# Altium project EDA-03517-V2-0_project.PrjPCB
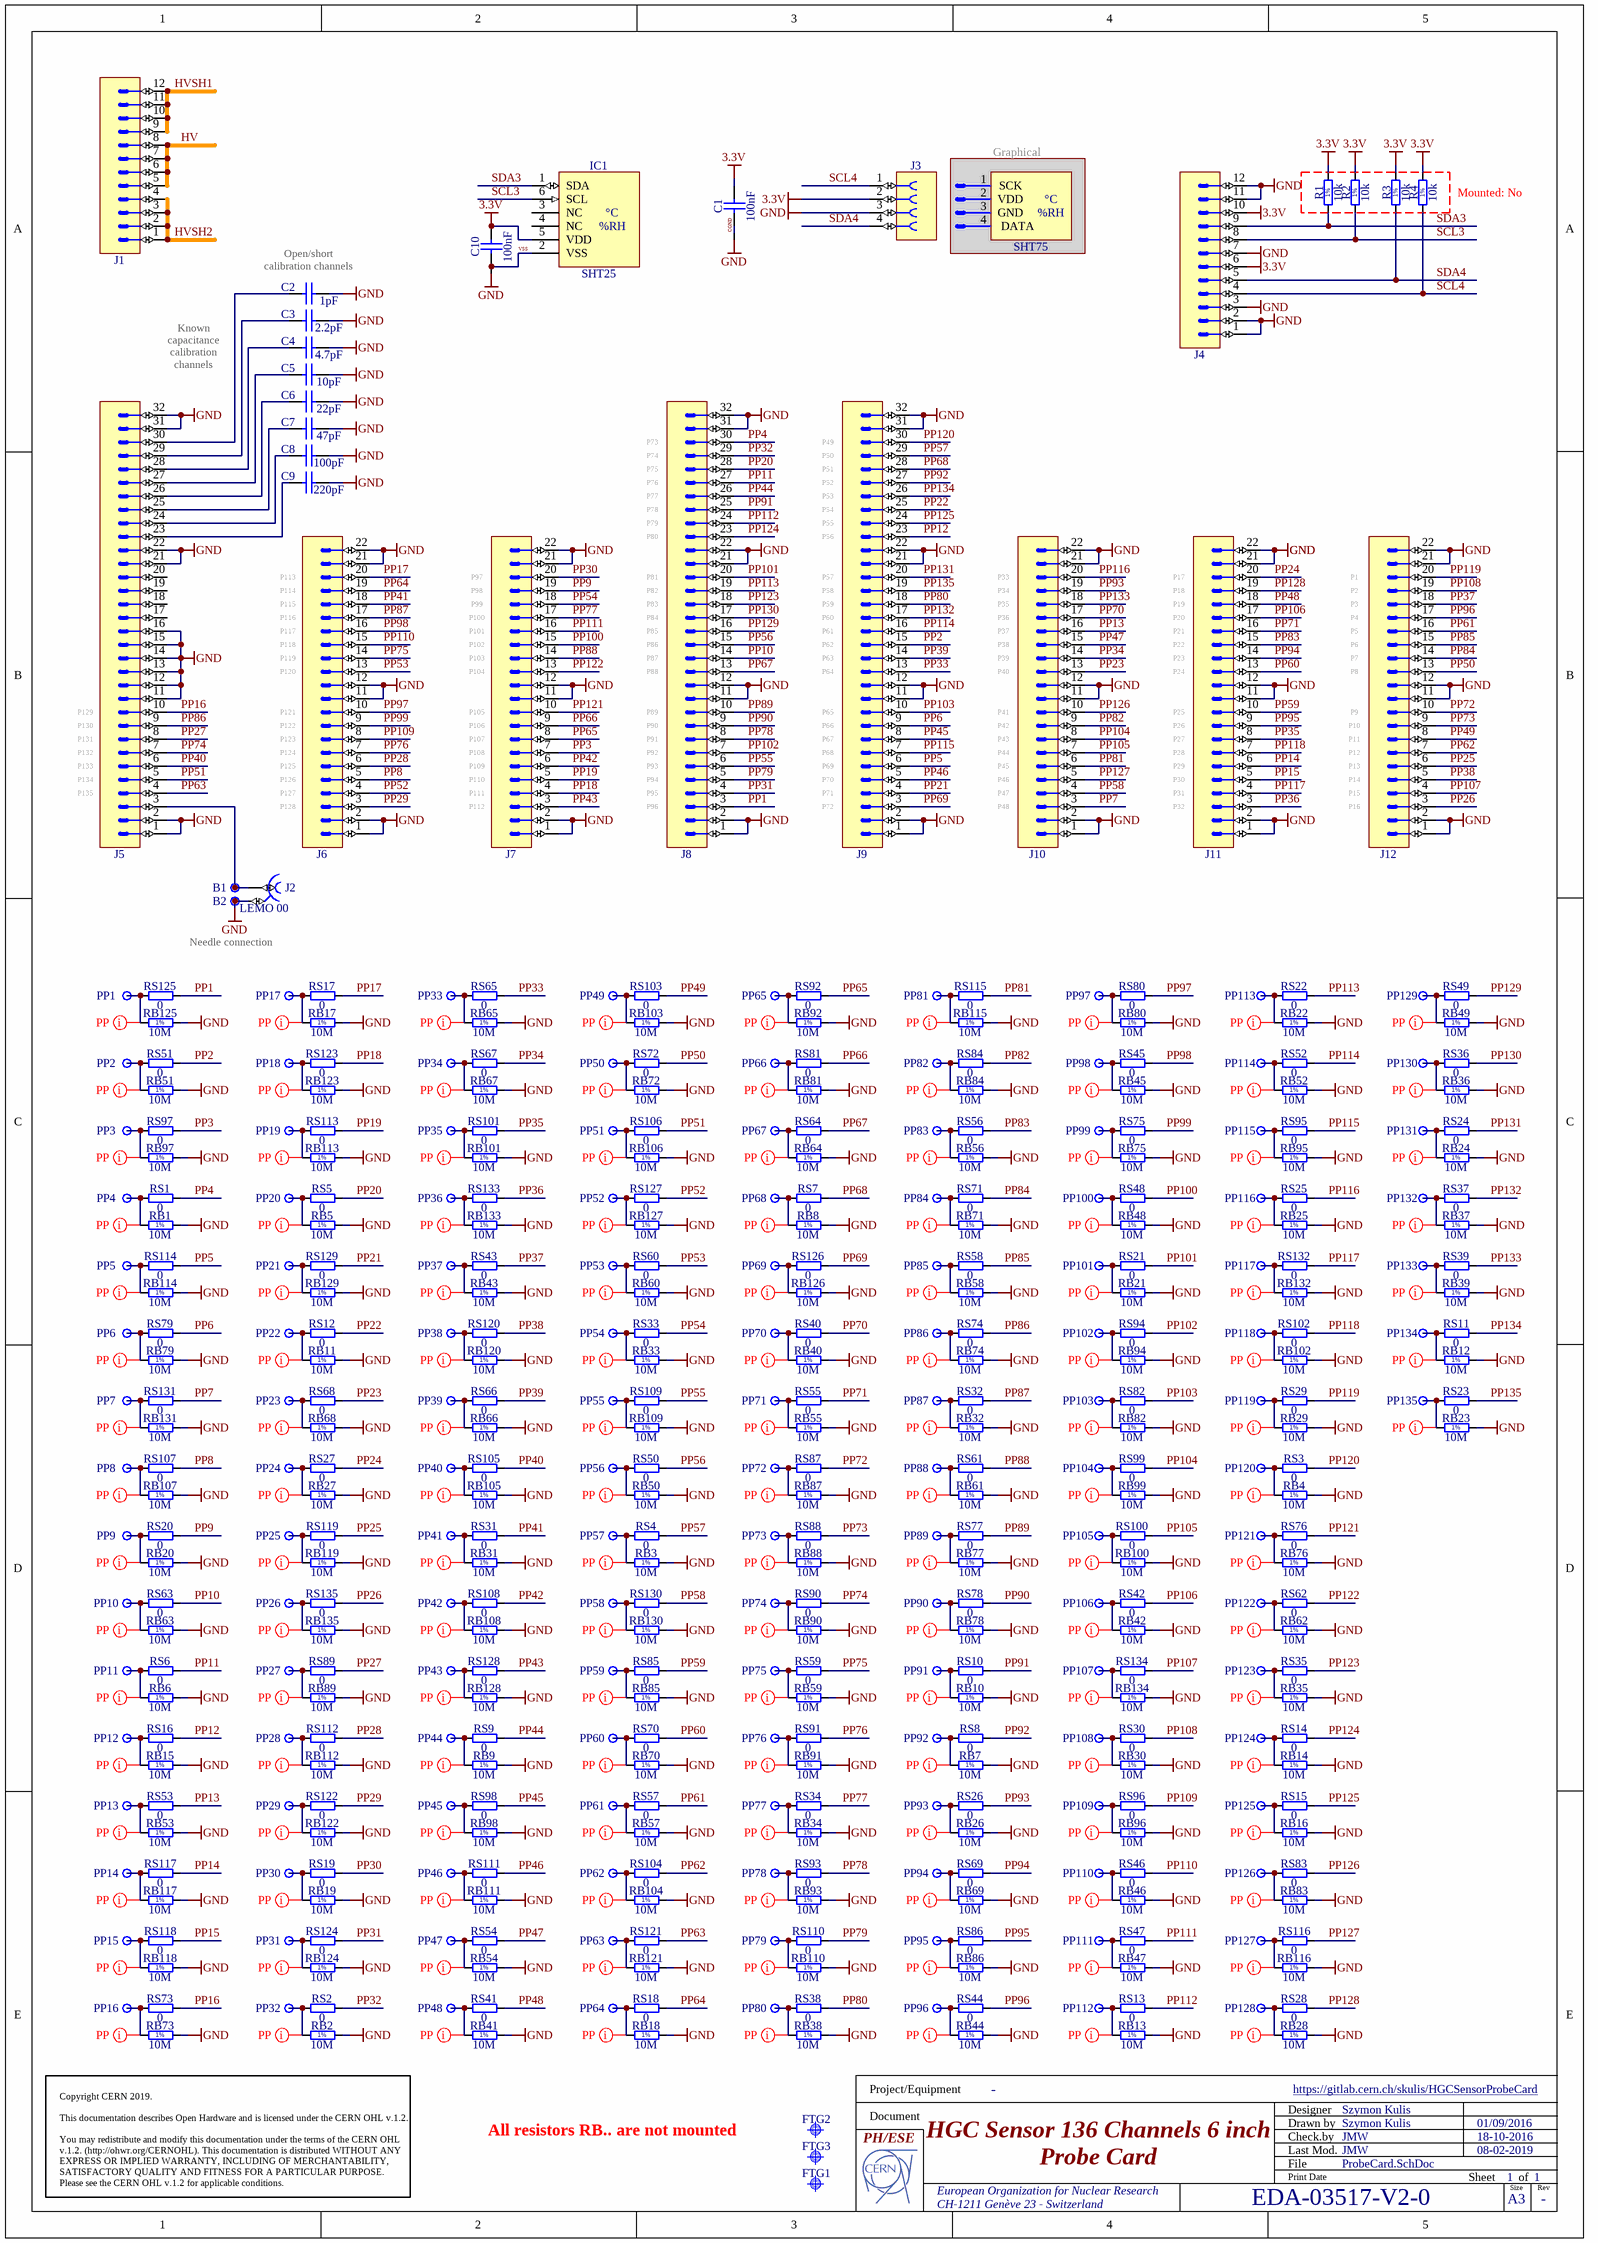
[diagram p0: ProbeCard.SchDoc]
1 sheet, 440 parts. Net scope: global (net labels, ports and power ports of the same name join across sheets).
Board file: EDA-03517-V2-0_pcb.pcbdoc

## Sheet ProbeCard.SchDoc: HGC Sensor 136 Channels 6 inch
size custom portrait; CheckedBy: JMW; Author: Szymon Kulis; CompanyName: CERN; DrawnBy: Szymon Kulis; Organization: CERN; Address1: European Organization for Nuclear Research; Address2: CH-1211 Genève 23 - Switzerland; Revision: -; SheetNumber: 1; SheetTotal: 1; EDA_Number: EDA-03517-V2-0; Projet: -; ModifiedBy: JMW; CreateDate: 01/09/2016; CheckedDate: 18-10-2016; Title2: Probe Card; DivGrp: PH/ESE; Designer: Szymon Kulis

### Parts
B1  IN  [c150h100]  (value not drawn)
B2  GND  [c150h100]  (value not drawn)
C1  100nF  [CAPC1608X87N]
C2  1pF  [CAPC1608X87N]
C3  2.2pF  [CAPC1608X87N]
C4  4.7pF  [CAPC1608X87N]
C5  10pF  [CAPC1608X87N]
C6  22pF  [CAPC1608X87N]
C7  47pF  [CAPC1608X87N]
C8  100pF  [CAPC1608X87N]
C9  220pF  [CAPC1608X87N]
C10  100nF  [CAPC1608X87N]
FTG1  Use only in PCB  [FIDUCIAL_TOP_C100-200]  (value not drawn)
FTG2  Use only in PCB  [FIDUCIAL_TOP_C100-200]  (value not drawn)
FTG3  Use only in PCB  [FIDUCIAL_TOP_C100-200]  (value not drawn)
Graphical  SHT75  (graphical)
IC1  SHT25  [SENSIRION_SHT2X]
J1  Header 12  [SAMTEC_MTLW-106-07-L-D-250]  (value not drawn)
J2  LEMO 00  [LEMO_EPK.00.250.NTN]
J3  Socket 4  [SAMTEC_SSW-104-02-L-S-RA]  (value not drawn)
J4  Header 12  [SAMTEC_MTLW-106-07-L-D-250]  (value not drawn)
J5  Header 32  [SAMTEC_MTLW-116-07-L-D-250]  (value not drawn)
J6  Header 22  [SAMTEC_MTLW-111-07-L-D-250]  (value not drawn)
J7  Header 22  [SAMTEC_MTLW-111-07-L-D-250]  (value not drawn)
J8  Header 32  [SAMTEC_MTLW-116-07-L-D-250]  (value not drawn)
J9  Header 32  [SAMTEC_MTLW-116-07-L-D-250]  (value not drawn)
J10  Header 22  [SAMTEC_MTLW-111-07-L-D-250]  (value not drawn)
J11  Header 22  [SAMTEC_MTLW-111-07-L-D-250]  (value not drawn)
J12  Header 22  [SAMTEC_MTLW-111-07-L-D-250]  (value not drawn)
NT1  Net Tie  [Net Tie]  (value not drawn)  (net tie, no BOM)
NT2  Net Tie  [Net Tie]  (value not drawn)  (net tie, no BOM)
PP1  Probe  [MILL-MAX_0985-1-15-20-71-14-11-0]  (value not drawn)
PP2  Probe  [MILL-MAX_0985-1-15-20-71-14-11-0]  (value not drawn)
PP3  Probe  [MILL-MAX_0985-1-15-20-71-14-11-0]  (value not drawn)
PP4  Probe  [MILL-MAX_0985-1-15-20-71-14-11-0]  (value not drawn)
PP5  Probe  [MILL-MAX_0985-1-15-20-71-14-11-0]  (value not drawn)
PP6  Probe  [MILL-MAX_0985-1-15-20-71-14-11-0]  (value not drawn)
PP7  Probe  [MILL-MAX_0985-1-15-20-71-14-11-0]  (value not drawn)
PP8  Probe  [MILL-MAX_0985-1-15-20-71-14-11-0]  (value not drawn)
PP9  Probe  [MILL-MAX_0985-1-15-20-71-14-11-0]  (value not drawn)
PP10  Probe  [MILL-MAX_0985-1-15-20-71-14-11-0]  (value not drawn)
PP11  Probe  [MILL-MAX_0985-1-15-20-71-14-11-0]  (value not drawn)
PP12  Probe  [MILL-MAX_0985-1-15-20-71-14-11-0]  (value not drawn)
PP13  Probe  [MILL-MAX_0985-1-15-20-71-14-11-0]  (value not drawn)
PP14  Probe  [MILL-MAX_0985-1-15-20-71-14-11-0]  (value not drawn)
PP15  Probe  [MILL-MAX_0985-1-15-20-71-14-11-0]  (value not drawn)
PP16  Probe  [MILL-MAX_0985-1-15-20-71-14-11-0]  (value not drawn)
PP17  Probe  [MILL-MAX_0985-1-15-20-71-14-11-0]  (value not drawn)
PP18  Probe  [MILL-MAX_0985-1-15-20-71-14-11-0]  (value not drawn)
PP19  Probe  [MILL-MAX_0985-1-15-20-71-14-11-0]  (value not drawn)
PP20  Probe  [MILL-MAX_0985-1-15-20-71-14-11-0]  (value not drawn)
PP21  Probe  [MILL-MAX_0985-1-15-20-71-14-11-0]  (value not drawn)
PP22  Probe  [MILL-MAX_0985-1-15-20-71-14-11-0]  (value not drawn)
PP23  Probe  [MILL-MAX_0985-1-15-20-71-14-11-0]  (value not drawn)
PP24  Probe  [MILL-MAX_0985-1-15-20-71-14-11-0]  (value not drawn)
PP25  Probe  [MILL-MAX_0985-1-15-20-71-14-11-0]  (value not drawn)
PP26  Probe  [MILL-MAX_0985-1-15-20-71-14-11-0]  (value not drawn)
PP27  Probe  [MILL-MAX_0985-1-15-20-71-14-11-0]  (value not drawn)
PP28  Probe  [MILL-MAX_0985-1-15-20-71-14-11-0]  (value not drawn)
PP29  Probe  [MILL-MAX_0985-1-15-20-71-14-11-0]  (value not drawn)
PP30  Probe  [MILL-MAX_0985-1-15-20-71-14-11-0]  (value not drawn)
PP31  Probe  [MILL-MAX_0985-1-15-20-71-14-11-0]  (value not drawn)
PP32  Probe  [MILL-MAX_0985-1-15-20-71-14-11-0]  (value not drawn)
PP33  Probe  [MILL-MAX_0985-1-15-20-71-14-11-0]  (value not drawn)
PP34  Probe  [MILL-MAX_0985-1-15-20-71-14-11-0]  (value not drawn)
PP35  Probe  [MILL-MAX_0985-1-15-20-71-14-11-0]  (value not drawn)
PP36  Probe  [MILL-MAX_0985-1-15-20-71-14-11-0]  (value not drawn)
PP37  Probe  [MILL-MAX_0985-1-15-20-71-14-11-0]  (value not drawn)
PP38  Probe  [MILL-MAX_0985-1-15-20-71-14-11-0]  (value not drawn)
PP39  Probe  [MILL-MAX_0985-1-15-20-71-14-11-0]  (value not drawn)
PP40  Probe  [MILL-MAX_0985-1-15-20-71-14-11-0]  (value not drawn)
PP41  Probe  [MILL-MAX_0985-1-15-20-71-14-11-0]  (value not drawn)
PP42  Probe  [MILL-MAX_0985-1-15-20-71-14-11-0]  (value not drawn)
PP43  Probe  [MILL-MAX_0985-1-15-20-71-14-11-0]  (value not drawn)
PP44  Probe  [MILL-MAX_0985-1-15-20-71-14-11-0]  (value not drawn)
PP45  Probe  [MILL-MAX_0985-1-15-20-71-14-11-0]  (value not drawn)
PP46  Probe  [MILL-MAX_0985-1-15-20-71-14-11-0]  (value not drawn)
PP47  Probe  [MILL-MAX_0985-1-15-20-71-14-11-0]  (value not drawn)
PP48  Probe  [MILL-MAX_0985-1-15-20-71-14-11-0]  (value not drawn)
PP49  Probe  [MILL-MAX_0985-1-15-20-71-14-11-0]  (value not drawn)
PP50  Probe  [MILL-MAX_0985-1-15-20-71-14-11-0]  (value not drawn)
PP51  Probe  [MILL-MAX_0985-1-15-20-71-14-11-0]  (value not drawn)
PP52  Probe  [MILL-MAX_0985-1-15-20-71-14-11-0]  (value not drawn)
PP53  Probe  [MILL-MAX_0985-1-15-20-71-14-11-0]  (value not drawn)
PP54  Probe  [MILL-MAX_0985-1-15-20-71-14-11-0]  (value not drawn)
PP55  Probe  [MILL-MAX_0985-1-15-20-71-14-11-0]  (value not drawn)
PP56  Probe  [MILL-MAX_0985-1-15-20-71-14-11-0]  (value not drawn)
PP57  Probe  [MILL-MAX_0985-1-15-20-71-14-11-0]  (value not drawn)
PP58  Probe  [MILL-MAX_0985-1-15-20-71-14-11-0]  (value not drawn)
PP59  Probe  [MILL-MAX_0985-1-15-20-71-14-11-0]  (value not drawn)
PP60  Probe  [MILL-MAX_0985-1-15-20-71-14-11-0]  (value not drawn)
PP61  Probe  [MILL-MAX_0985-1-15-20-71-14-11-0]  (value not drawn)
PP62  Probe  [MILL-MAX_0985-1-15-20-71-14-11-0]  (value not drawn)
PP63  Probe  [MILL-MAX_0985-1-15-20-71-14-11-0]  (value not drawn)
PP64  Probe  [MILL-MAX_0985-1-15-20-71-14-11-0]  (value not drawn)
PP65  Probe  [MILL-MAX_0985-1-15-20-71-14-11-0]  (value not drawn)
PP66  Probe  [MILL-MAX_0985-1-15-20-71-14-11-0]  (value not drawn)
PP67  Probe  [MILL-MAX_0985-1-15-20-71-14-11-0]  (value not drawn)
PP68  Probe  [MILL-MAX_0985-1-15-20-71-14-11-0]  (value not drawn)
PP69  Probe  [MILL-MAX_0985-1-15-20-71-14-11-0]  (value not drawn)
PP70  Probe  [MILL-MAX_0985-1-15-20-71-14-11-0]  (value not drawn)
PP71  Probe  [MILL-MAX_0985-1-15-20-71-14-11-0]  (value not drawn)
PP72  Probe  [MILL-MAX_0985-1-15-20-71-14-11-0]  (value not drawn)
PP73  Probe  [MILL-MAX_0985-1-15-20-71-14-11-0]  (value not drawn)
PP74  Probe  [MILL-MAX_0985-1-15-20-71-14-11-0]  (value not drawn)
PP75  Probe  [MILL-MAX_0985-1-15-20-71-14-11-0]  (value not drawn)
PP76  Probe  [MILL-MAX_0985-1-15-20-71-14-11-0]  (value not drawn)
PP77  Probe  [MILL-MAX_0985-1-15-20-71-14-11-0]  (value not drawn)
PP78  Probe  [MILL-MAX_0985-1-15-20-71-14-11-0]  (value not drawn)
PP79  Probe  [MILL-MAX_0985-1-15-20-71-14-11-0]  (value not drawn)
PP80  Probe  [MILL-MAX_0985-1-15-20-71-14-11-0]  (value not drawn)
PP81  Probe  [MILL-MAX_0985-1-15-20-71-14-11-0]  (value not drawn)
PP82  Probe  [MILL-MAX_0985-1-15-20-71-14-11-0]  (value not drawn)
PP83  Probe  [MILL-MAX_0985-1-15-20-71-14-11-0]  (value not drawn)
PP84  Probe  [MILL-MAX_0985-1-15-20-71-14-11-0]  (value not drawn)
PP85  Probe  [MILL-MAX_0985-1-15-20-71-14-11-0]  (value not drawn)
PP86  Probe  [MILL-MAX_0985-1-15-20-71-14-11-0]  (value not drawn)
PP87  Probe  [MILL-MAX_0985-1-15-20-71-14-11-0]  (value not drawn)
PP88  Probe  [MILL-MAX_0985-1-15-20-71-14-11-0]  (value not drawn)
PP89  Probe  [MILL-MAX_0985-1-15-20-71-14-11-0]  (value not drawn)
PP90  Probe  [MILL-MAX_0985-1-15-20-71-14-11-0]  (value not drawn)
PP91  Probe  [MILL-MAX_0985-1-15-20-71-14-11-0]  (value not drawn)
PP92  Probe  [MILL-MAX_0985-1-15-20-71-14-11-0]  (value not drawn)
PP93  Probe  [MILL-MAX_0985-1-15-20-71-14-11-0]  (value not drawn)
PP94  Probe  [MILL-MAX_0985-1-15-20-71-14-11-0]  (value not drawn)
PP95  Probe  [MILL-MAX_0985-1-15-20-71-14-11-0]  (value not drawn)
PP96  Probe  [MILL-MAX_0985-1-15-20-71-14-11-0]  (value not drawn)
PP97  Probe  [MILL-MAX_0985-1-15-20-71-14-11-0]  (value not drawn)
PP98  Probe  [MILL-MAX_0985-1-15-20-71-14-11-0]  (value not drawn)
PP99  Probe  [MILL-MAX_0985-1-15-20-71-14-11-0]  (value not drawn)
PP100  Probe  [MILL-MAX_0985-1-15-20-71-14-11-0]  (value not drawn)
PP101  Probe  [MILL-MAX_0985-1-15-20-71-14-11-0]  (value not drawn)
PP102  Probe  [MILL-MAX_0985-1-15-20-71-14-11-0]  (value not drawn)
PP103  Probe  [MILL-MAX_0985-1-15-20-71-14-11-0]  (value not drawn)
PP104  Probe  [MILL-MAX_0985-1-15-20-71-14-11-0]  (value not drawn)
PP105  Probe  [MILL-MAX_0985-1-15-20-71-14-11-0]  (value not drawn)
PP106  Probe  [MILL-MAX_0985-1-15-20-71-14-11-0]  (value not drawn)
PP107  Probe  [MILL-MAX_0985-1-15-20-71-14-11-0]  (value not drawn)
PP108  Probe  [MILL-MAX_0985-1-15-20-71-14-11-0]  (value not drawn)
PP109  Probe  [MILL-MAX_0985-1-15-20-71-14-11-0]  (value not drawn)
PP110  Probe  [MILL-MAX_0985-1-15-20-71-14-11-0]  (value not drawn)
PP111  Probe  [MILL-MAX_0985-1-15-20-71-14-11-0]  (value not drawn)
PP112  Probe  [MILL-MAX_0985-1-15-20-71-14-11-0]  (value not drawn)
PP113  Probe  [MILL-MAX_0985-1-15-20-71-14-11-0]  (value not drawn)
PP114  Probe  [MILL-MAX_0985-1-15-20-71-14-11-0]  (value not drawn)
PP115  Probe  [MILL-MAX_0985-1-15-20-71-14-11-0]  (value not drawn)
PP116  Probe  [MILL-MAX_0985-1-15-20-71-14-11-0]  (value not drawn)
PP117  Probe  [MILL-MAX_0985-1-15-20-71-14-11-0]  (value not drawn)
PP118  Probe  [MILL-MAX_0985-1-15-20-71-14-11-0]  (value not drawn)
PP119  Probe  [MILL-MAX_0985-1-15-20-71-14-11-0]  (value not drawn)
PP120  Probe  [MILL-MAX_0985-1-15-20-71-14-11-0]  (value not drawn)
PP121  Probe  [MILL-MAX_0985-1-15-20-71-14-11-0]  (value not drawn)
PP122  Probe  [MILL-MAX_0985-1-15-20-71-14-11-0]  (value not drawn)
PP123  Probe  [MILL-MAX_0985-1-15-20-71-14-11-0]  (value not drawn)
PP124  Probe  [MILL-MAX_0985-1-15-20-71-14-11-0]  (value not drawn)
PP125  Probe  [MILL-MAX_0985-1-15-20-71-14-11-0]  (value not drawn)
PP126  Probe  [MILL-MAX_0985-1-15-20-71-14-11-0]  (value not drawn)
PP127  Probe  [MILL-MAX_0985-1-15-20-71-14-11-0]  (value not drawn)
PP128  Probe  [MILL-MAX_0985-1-15-20-71-14-11-0]  (value not drawn)
PP129  Probe  [MILL-MAX_0985-1-15-20-71-14-11-0]  (value not drawn)
PP130  Probe  [MILL-MAX_0985-1-15-20-71-14-11-0]  (value not drawn)
PP131  Probe  [MILL-MAX_0985-1-15-20-71-14-11-0]  (value not drawn)
PP132  Probe  [MILL-MAX_0985-1-15-20-71-14-11-0]  (value not drawn)
PP133  Probe  [MILL-MAX_0985-1-15-20-71-14-11-0]  (value not drawn)
PP134  Probe  [MILL-MAX_0985-1-15-20-71-14-11-0]  (value not drawn)
PP135  Probe  [MILL-MAX_0985-1-15-20-71-14-11-0]  (value not drawn)
R1  10k  [RESC1608X55N]
R2  10k  [RESC1608X55N]
R3  10k  [RESC1608X55N]
R4  10k  Mounted: No  [RESC1608X55N]
RB1  10M  [RESC1508X63N]
RB2  10M  [RESC1508X63N]
RB3  10M  [RESC1508X63N]
RB4  10M  [RESC1508X63N]
RB5  10M  [RESC1508X63N]
RB6  10M  [RESC1508X63N]
RB7  10M  [RESC1508X63N]
RB8  10M  [RESC1508X63N]
RB9  10M  [RESC1508X63N]
RB10  10M  [RESC1508X63N]
RB11  10M  [RESC1508X63N]
RB12  10M  [RESC1508X63N]
RB13  10M  [RESC1508X63N]
RB14  10M  [RESC1508X63N]
RB15  10M  [RESC1508X63N]
RB16  10M  [RESC1508X63N]
RB17  10M  [RESC1508X63N]
RB18  10M  [RESC1508X63N]
RB19  10M  [RESC1508X63N]
RB20  10M  [RESC1508X63N]
RB21  10M  [RESC1508X63N]
RB22  10M  [RESC1508X63N]
RB23  10M  [RESC1508X63N]
RB24  10M  [RESC1508X63N]
RB25  10M  [RESC1508X63N]
RB26  10M  [RESC1508X63N]
RB27  10M  [RESC1508X63N]
RB28  10M  [RESC1508X63N]
RB29  10M  [RESC1508X63N]
RB30  10M  [RESC1508X63N]
RB31  10M  [RESC1508X63N]
RB32  10M  [RESC1508X63N]
RB33  10M  [RESC1508X63N]
RB34  10M  [RESC1508X63N]
RB35  10M  [RESC1508X63N]
RB36  10M  [RESC1508X63N]
RB37  10M  [RESC1508X63N]
RB38  10M  [RESC1508X63N]
RB39  10M  [RESC1508X63N]
RB40  10M  [RESC1508X63N]
RB41  10M  [RESC1508X63N]
RB42  10M  [RESC1508X63N]
RB43  10M  [RESC1508X63N]
RB44  10M  [RESC1508X63N]
RB45  10M  [RESC1508X63N]
RB46  10M  [RESC1508X63N]
RB47  10M  [RESC1508X63N]
RB48  10M  [RESC1508X63N]
RB49  10M  [RESC1508X63N]
RB50  10M  [RESC1508X63N]
RB51  10M  [RESC1508X63N]
RB52  10M  [RESC1508X63N]
RB53  10M  [RESC1508X63N]
RB54  10M  [RESC1508X63N]
RB55  10M  [RESC1508X63N]
RB56  10M  [RESC1508X63N]
RB57  10M  [RESC1508X63N]
RB58  10M  [RESC1508X63N]
RB59  10M  [RESC1508X63N]
RB60  10M  [RESC1508X63N]
RB61  10M  [RESC1508X63N]
RB62  10M  [RESC1508X63N]
RB63  10M  [RESC1508X63N]
RB64  10M  [RESC1508X63N]
RB65  10M  [RESC1508X63N]
RB66  10M  [RESC1508X63N]
RB67  10M  [RESC1508X63N]
RB68  10M  [RESC1508X63N]
RB69  10M  [RESC1508X63N]
RB70  10M  [RESC1508X63N]
RB71  10M  [RESC1508X63N]
RB72  10M  [RESC1508X63N]
RB73  10M  [RESC1508X63N]
RB74  10M  [RESC1508X63N]
RB75  10M  [RESC1508X63N]
RB76  10M  [RESC1508X63N]
RB77  10M  [RESC1508X63N]
RB78  10M  [RESC1508X63N]
RB79  10M  [RESC1508X63N]
RB80  10M  [RESC1508X63N]
RB81  10M  [RESC1508X63N]
RB82  10M  [RESC1508X63N]
RB83  10M  [RESC1508X63N]
RB84  10M  [RESC1508X63N]
RB85  10M  [RESC1508X63N]
RB86  10M  [RESC1508X63N]
RB87  10M  [RESC1508X63N]
RB88  10M  [RESC1508X63N]
RB89  10M  [RESC1508X63N]
RB90  10M  [RESC1508X63N]
RB91  10M  [RESC1508X63N]
RB92  10M  [RESC1508X63N]
RB93  10M  [RESC1508X63N]
RB94  10M  [RESC1508X63N]
RB95  10M  [RESC1508X63N]
RB96  10M  [RESC1508X63N]
RB97  10M  [RESC1508X63N]
RB98  10M  [RESC1508X63N]
RB99  10M  [RESC1508X63N]
RB100  10M  [RESC1508X63N]
RB101  10M  [RESC1508X63N]
RB102  10M  [RESC1508X63N]
RB103  10M  [RESC1508X63N]
RB104  10M  [RESC1508X63N]
RB105  10M  [RESC1508X63N]
RB106  10M  [RESC1508X63N]
RB107  10M  [RESC1508X63N]
RB108  10M  [RESC1508X63N]
RB109  10M  [RESC1508X63N]
RB110  10M  [RESC1508X63N]
RB111  10M  [RESC1508X63N]
RB112  10M  [RESC1508X63N]
RB113  10M  [RESC1508X63N]
RB114  10M  [RESC1508X63N]
RB115  10M  [RESC1508X63N]
RB116  10M  [RESC1508X63N]
RB117  10M  [RESC1508X63N]
RB118  10M  [RESC1508X63N]
RB119  10M  [RESC1508X63N]
RB120  10M  [RESC1508X63N]
RB121  10M  [RESC1508X63N]
RB122  10M  [RESC1508X63N]
RB123  10M  [RESC1508X63N]
RB124  10M  [RESC1508X63N]
RB125  10M  [RESC1508X63N]
RB126  10M  [RESC1508X63N]
RB127  10M  [RESC1508X63N]
RB128  10M  [RESC1508X63N]
RB129  10M  [RESC1508X63N]
RB130  10M  [RESC1508X63N]
RB131  10M  [RESC1508X63N]
RB132  10M  [RESC1508X63N]
RB133  10M  [RESC1508X63N]
RB134  10M  [RESC1508X63N]
RB135  10M  [RESC1508X63N]
RS1  0  [RESC1608X55N]
RS2  0  [RESC1608X55N]
RS3  0  [RESC1608X55N]
RS4  0  [RESC1608X55N]
RS5  0  [RESC1608X55N]
RS6  0  [RESC1608X55N]
RS7  0  [RESC1608X55N]
RS8  0  [RESC1608X55N]
RS9  0  [RESC1608X55N]
RS10  0  [RESC1608X55N]
RS11  0  [RESC1608X55N]
RS12  0  [RESC1608X55N]
RS13  0  [RESC1608X55N]
RS14  0  [RESC1608X55N]
RS15  0  [RESC1608X55N]
RS16  0  [RESC1608X55N]
RS17  0  [RESC1608X55N]
RS18  0  [RESC1608X55N]
RS19  0  [RESC1608X55N]
RS20  0  [RESC1608X55N]
RS21  0  [RESC1608X55N]
RS22  0  [RESC1608X55N]
RS23  0  [RESC1608X55N]
RS24  0  [RESC1608X55N]
RS25  0  [RESC1608X55N]
RS26  0  [RESC1608X55N]
RS27  0  [RESC1608X55N]
RS28  0  [RESC1608X55N]
RS29  0  [RESC1608X55N]
RS30  0  [RESC1608X55N]
RS31  0  [RESC1608X55N]
RS32  0  [RESC1608X55N]
RS33  0  [RESC1608X55N]
RS34  0  [RESC1608X55N]
RS35  0  [RESC1608X55N]
RS36  0  [RESC1608X55N]
RS37  0  [RESC1608X55N]
RS38  0  [RESC1608X55N]
RS39  0  [RESC1608X55N]
RS40  0  [RESC1608X55N]
RS41  0  [RESC1608X55N]
RS42  0  [RESC1608X55N]
RS43  0  [RESC1608X55N]
RS44  0  [RESC1608X55N]
RS45  0  [RESC1608X55N]
RS46  0  [RESC1608X55N]
RS47  0  [RESC1608X55N]
RS48  0  [RESC1608X55N]
RS49  0  [RESC1608X55N]
RS50  0  [RESC1608X55N]
RS51  0  [RESC1608X55N]
RS52  0  [RESC1608X55N]
RS53  0  [RESC1608X55N]
RS54  0  [RESC1608X55N]
RS55  0  [RESC1608X55N]
RS56  0  [RESC1608X55N]
RS57  0  [RESC1608X55N]
RS58  0  [RESC1608X55N]
RS59  0  [RESC1608X55N]
RS60  0  [RESC1608X55N]
RS61  0  [RESC1608X55N]
RS62  0  [RESC1608X55N]
RS63  0  [RESC1608X55N]
RS64  0  [RESC1608X55N]
RS65  0  [RESC1608X55N]
RS66  0  [RESC1608X55N]
RS67  0  [RESC1608X55N]
RS68  0  [RESC1608X55N]
RS69  0  [RESC1608X55N]
RS70  0  [RESC1608X55N]
RS71  0  [RESC1608X55N]
RS72  0  [RESC1608X55N]
RS73  0  [RESC1608X55N]
RS74  0  [RESC1608X55N]
RS75  0  [RESC1608X55N]
RS76  0  [RESC1608X55N]
RS77  0  [RESC1608X55N]
RS78  0  [RESC1608X55N]
RS79  0  [RESC1608X55N]
RS80  0  [RESC1608X55N]
RS81  0  [RESC1608X55N]
RS82  0  [RESC1608X55N]
RS83  0  [RESC1608X55N]
RS84  0  [RESC1608X55N]
RS85  0  [RESC1608X55N]
RS86  0  [RESC1608X55N]
RS87  0  [RESC1608X55N]
RS88  0  [RESC1608X55N]
RS89  0  [RESC1608X55N]
RS90  0  [RESC1608X55N]
RS91  0  [RESC1608X55N]
RS92  0  [RESC1608X55N]
RS93  0  [RESC1608X55N]
RS94  0  [RESC1608X55N]
RS95  0  [RESC1608X55N]
RS96  0  [RESC1608X55N]
RS97  0  [RESC1608X55N]
RS98  0  [RESC1608X55N]
RS99  0  [RESC1608X55N]
RS100  0  [RESC1608X55N]
RS101  0  [RESC1608X55N]
RS102  0  [RESC1608X55N]
RS103  0  [RESC1608X55N]
RS104  0  [RESC1608X55N]
RS105  0  [RESC1608X55N]
RS106  0  [RESC1608X55N]
RS107  0  [RESC1608X55N]
RS108  0  [RESC1608X55N]
RS109  0  [RESC1608X55N]
RS110  0  [RESC1608X55N]
RS111  0  [RESC1608X55N]
RS112  0  [RESC1608X55N]
RS113  0  [RESC1608X55N]
RS114  0  [RESC1608X55N]
RS115  0  [RESC1608X55N]
RS116  0  [RESC1608X55N]
RS117  0  [RESC1608X55N]
RS118  0  [RESC1608X55N]
RS119  0  [RESC1608X55N]
RS120  0  [RESC1608X55N]
RS121  0  [RESC1608X55N]
RS122  0  [RESC1608X55N]
RS123  0  [RESC1608X55N]
RS124  0  [RESC1608X55N]
RS125  0  [RESC1608X55N]
RS126  0  [RESC1608X55N]
RS127  0  [RESC1608X55N]
RS128  0  [RESC1608X55N]
RS129  0  [RESC1608X55N]
RS130  0  [RESC1608X55N]
RS131  0  [RESC1608X55N]
RS132  0  [RESC1608X55N]
RS133  0  [RESC1608X55N]
RS134  0  [RESC1608X55N]
RS135  0  [RESC1608X55N]

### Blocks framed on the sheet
Graphical: Graphical

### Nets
3.3V: C1.2 C10.2 IC1.5(VDD) J3.2 J4.6 J4.10 R1.2 R2.2 R3.2 R4.2
GND: B2.1 C2.2 C3.2 C4.2 C5.2 C6.2 C7.2 C8.2 C9.2 J2.2 J3.3 J4.1 J4.2 J4.3 J4.7 J4.11 J4.12 J5.1 J5.2 J5.11 J5.12 J5.13 J5.14 J5.15 J5.16 J5.21 J5.22 J5.31 J5.32 J6.1 J6.2 J6.11 J6.12 J6.21 J6.22 J7.1 J7.2 J7.11 J7.12 J7.21 J7.22 J8.1 J8.2 J8.11 J8.12 J8.21 J8.22 J8.31 J8.32 J9.1 J9.2 J9.11 J9.12 J9.21 J9.22 J9.31 J9.32 J10.1 J10.2 J10.11 J10.12 J10.21 J10.22 J11.1 J11.2 J11.11 J11.12 J11.21 J11.22 J12.1 J12.2 J12.11 J12.12 J12.21 J12.22 NT1.1 NT2.1 RB1.2 RB2.2 RB3.2 RB4.2 RB5.2 RB6.2 RB7.2 RB8.2 RB9.2 RB10.2 RB11.2 RB12.2 RB13.2 RB14.2 RB15.2 RB16.2 RB17.2 RB18.2 RB19.2 RB20.2 RB21.2 RB22.2 RB23.2 RB24.2 RB25.2 RB26.2 RB27.2 RB28.2 RB29.2 RB30.2 RB31.2 RB32.2 RB33.2 RB34.2 RB35.2 RB36.2 RB37.2 RB38.2 RB39.2 RB40.2 RB41.2 RB42.2 RB43.2 RB44.2 RB45.2 RB46.2 RB47.2 RB48.2 RB49.2 RB50.2 RB51.2 RB52.2 RB53.2 RB54.2 RB55.2 RB56.2 RB57.2 RB58.2 RB59.2 RB60.2 RB61.2 RB62.2 RB63.2 RB64.2 RB65.2 RB66.2 RB67.2 RB68.2 RB69.2 RB70.2 RB71.2 RB72.2 RB73.2 RB74.2 RB75.2 RB76.2 RB77.2 RB78.2 RB79.2 RB80.2 RB81.2 RB82.2 RB83.2 RB84.2 RB85.2 RB86.2 RB87.2 RB88.2 RB89.2 RB90.2 RB91.2 RB92.2 RB93.2 RB94.2 RB95.2 RB96.2 RB97.2 RB98.2 RB99.2 RB100.2 RB101.2 RB102.2 RB103.2 RB104.2 RB105.2 RB106.2 RB107.2 RB108.2 RB109.2 RB110.2 RB111.2 RB112.2 RB113.2 RB114.2 RB115.2 RB116.2 RB117.2 RB118.2 RB119.2 RB120.2 RB121.2 RB122.2 RB123.2 RB124.2 RB125.2 RB126.2 RB127.2 RB128.2 RB129.2 RB130.2 RB131.2 RB132.2 RB133.2 RB134.2 RB135.2
VSS: C10.1 IC1.2(VSS) IC1.7(EP) NT1.2
CGND: C1.1 NT2.2
HV: J1.5 J1.6 J1.7 J1.8
HVSH1: J1.9 J1.10 J1.11 J1.12
HVSH2: J1.1 J1.2 J1.3 J1.4
PP1: J8.3 RS125.2
PP2: J9.15 RS51.2
PP3: J7.7 RS97.2
PP4: J8.30 RS1.2
PP5: J9.6 RS114.2
PP6: J9.9 RS79.2
PP7: J10.3 RS131.2
PP8: J6.5 RS107.2
PP9: J7.19 RS20.2
PP10: J8.14 RS63.2
PP11: J8.27 RS6.2
PP12: J9.23 RS16.2
PP13: J10.16 RS53.2
PP14: J11.6 RS117.2
PP15: J11.5 RS118.2
PP16: J5.10 RS73.2
PP17: J6.20 RS17.2
PP18: J7.4 RS123.2
PP19: J7.5 RS113.2
PP20: J8.28 RS5.2
PP21: J9.4 RS129.2
PP22: J9.25 RS12.2
PP23: J10.13 RS68.2
PP24: J11.20 RS27.2
PP25: J12.6 RS119.2
PP26: J12.3 RS135.2
PP27: J5.8 RS89.2
PP28: J6.6 RS112.2
PP29: J6.3 RS122.2
PP30: J7.20 RS19.2
PP31: J8.4 RS124.2
PP32: J8.29 RS2.2
PP33: J9.13 RS65.2
PP34: J10.14 RS67.2
PP35: J11.8 RS101.2
PP36: J11.3 RS133.2
PP37: J12.18 RS43.2
PP38: J12.5 RS120.2
PP39: J9.14 RS66.2
PP40: J5.6 RS105.2
PP41: J6.18 RS31.2
PP42: J7.6 RS108.2
PP43: J7.3 RS128.2
PP44: J8.26 RS9.2
PP45: J9.8 RS98.2
PP46: J9.5 RS111.2
PP47: J10.15 RS54.2
PP48: J11.18 RS41.2
PP49: J12.8 RS103.2
PP50: J12.13 RS72.2
PP51: J5.5 RS106.2
PP52: J6.4 RS127.2
PP53: J6.13 RS60.2
PP54: J7.18 RS33.2
PP55: J8.6 RS109.2
PP56: J8.15 RS50.2
PP57: J9.29 RS4.2
PP58: J10.4 RS130.2
PP59: J11.10 RS85.2
PP60: J11.13 RS70.2
PP61: J12.16 RS57.2
PP62: J12.7 RS104.2
PP63: J5.4 RS121.2
PP64: J6.19 RS18.2
PP65: J7.8 RS92.2
PP66: J7.9 RS81.2
PP67: J8.13 RS64.2
PP68: J9.28 RS7.2
PP69: J9.3 RS126.2
PP70: J10.17 RS40.2
PP71: J11.16 RS55.2
PP72: J12.10 RS87.2
PP73: J12.9 RS88.2
PP74: J5.7 RS90.2
PP75: J6.14 RS59.2
PP76: J6.7 RS91.2
PP77: J7.17 RS34.2
PP78: J8.8 RS93.2
PP79: J8.5 RS110.2
PP80: J9.18 RS38.2
PP81: J10.6 RS115.2
PP82: J10.9 RS84.2
PP83: J11.15 RS56.2
PP84: J12.14 RS71.2
PP85: J12.15 RS58.2
PP86: J5.9 RS74.2
PP87: J6.17 RS32.2
PP88: J7.14 RS61.2
PP89: J8.10 RS77.2
PP90: J8.9 RS78.2
PP91: J8.25 RS10.2
PP92: J9.27 RS8.2
PP93: J10.19 RS26.2
PP94: J11.14 RS69.2
PP95: J11.9 RS86.2
PP96: J12.17 RS44.2
PP97: J6.10 RS80.2
PP98: J6.16 RS45.2
PP99: J6.9 RS75.2
PP100: J7.15 RS48.2
PP101: J8.20 RS21.2
PP102: J8.7 RS94.2
PP103: J9.10 RS82.2
PP104: J10.8 RS99.2
PP105: J10.7 RS100.2
PP106: J11.17 RS42.2
PP107: J12.4 RS134.2
PP108: J12.19 RS30.2
PP109: J6.8 RS96.2
PP110: J6.15 RS46.2
PP111: J7.16 RS47.2
PP112: J8.24 RS13.2
PP113: J8.19 RS22.2
PP114: J9.16 RS52.2
PP115: J9.7 RS95.2
PP116: J10.20 RS25.2
PP117: J11.4 RS132.2
PP118: J11.7 RS102.2
PP119: J12.20 RS29.2
PP120: J9.30 RS3.2
PP121: J7.10 RS76.2
PP122: J7.13 RS62.2
PP123: J8.18 RS35.2
PP124: J8.23 RS14.2
PP125: J9.24 RS15.2
PP126: J10.10 RS83.2
PP127: J10.5 RS116.2
PP128: J11.19 RS28.2
PP129: J8.16 RS49.2
PP130: J8.17 RS36.2
PP131: J9.20 RS24.2
PP132: J9.17 RS37.2
PP133: J10.18 RS39.2
PP134: J9.26 RS11.2
PP135: J9.19 RS23.2
SCL3: IC1.6(SCL) J4.8 R2.1
SCL4: J3.1 J4.4 R4.1
SDA3: IC1.1(SDA) J4.9 R1.1
SDA4: J3.4 J4.5 R3.1
NetB1_1: B1.1 J2.1 J5.3
NetC2_1: C2.1 J5.30
NetC3_1: C3.1 J5.29
NetC4_1: C4.1 J5.28
NetC5_1: C5.1 J5.27
NetC6_1: C6.1 J5.26
NetC7_1: C7.1 J5.25
NetC8_1: C8.1 J5.24
NetC9_1: C9.1 J5.23
NetPP1_1: PP1.1 RB125.1 RS125.1
NetPP2_1: PP2.1 RB51.1 RS51.1
NetPP3_1: PP3.1 RB97.1 RS97.1
NetPP4_1: PP4.1 RB1.1 RS1.1
NetPP5_1: PP5.1 RB114.1 RS114.1
NetPP6_1: PP6.1 RB79.1 RS79.1
NetPP7_1: PP7.1 RB131.1 RS131.1
NetPP8_1: PP8.1 RB107.1 RS107.1
NetPP9_1: PP9.1 RB20.1 RS20.1
NetPP10_1: PP10.1 RB63.1 RS63.1
NetPP11_1: PP11.1 RB6.1 RS6.1
NetPP12_1: PP12.1 RB15.1 RS16.1
NetPP13_1: PP13.1 RB53.1 RS53.1
NetPP14_1: PP14.1 RB117.1 RS117.1
NetPP15_1: PP15.1 RB118.1 RS118.1
NetPP16_1: PP16.1 RB73.1 RS73.1
NetPP17_1: PP17.1 RB17.1 RS17.1
NetPP18_1: PP18.1 RB123.1 RS123.1
NetPP19_1: PP19.1 RB113.1 RS113.1
NetPP20_1: PP20.1 RB5.1 RS5.1
NetPP21_1: PP21.1 RB129.1 RS129.1
NetPP22_1: PP22.1 RB11.1 RS12.1
NetPP23_1: PP23.1 RB68.1 RS68.1
NetPP24_1: PP24.1 RB27.1 RS27.1
NetPP25_1: PP25.1 RB119.1 RS119.1
NetPP26_1: PP26.1 RB135.1 RS135.1
NetPP27_1: PP27.1 RB89.1 RS89.1
NetPP28_1: PP28.1 RB112.1 RS112.1
NetPP29_1: PP29.1 RB122.1 RS122.1
NetPP30_1: PP30.1 RB19.1 RS19.1
NetPP31_1: PP31.1 RB124.1 RS124.1
NetPP32_1: PP32.1 RB2.1 RS2.1
NetPP33_1: PP33.1 RB65.1 RS65.1
NetPP34_1: PP34.1 RB67.1 RS67.1
NetPP35_1: PP35.1 RB101.1 RS101.1
NetPP36_1: PP36.1 RB133.1 RS133.1
NetPP37_1: PP37.1 RB43.1 RS43.1
NetPP38_1: PP38.1 RB120.1 RS120.1
NetPP39_1: PP39.1 RB66.1 RS66.1
NetPP40_1: PP40.1 RB105.1 RS105.1
NetPP41_1: PP41.1 RB31.1 RS31.1
NetPP42_1: PP42.1 RB108.1 RS108.1
NetPP43_1: PP43.1 RB128.1 RS128.1
NetPP44_1: PP44.1 RB9.1 RS9.1
NetPP45_1: PP45.1 RB98.1 RS98.1
NetPP46_1: PP46.1 RB111.1 RS111.1
NetPP47_1: PP47.1 RB54.1 RS54.1
NetPP48_1: PP48.1 RB41.1 RS41.1
NetPP49_1: PP49.1 RB103.1 RS103.1
NetPP50_1: PP50.1 RB72.1 RS72.1
NetPP51_1: PP51.1 RB106.1 RS106.1
NetPP52_1: PP52.1 RB127.1 RS127.1
NetPP53_1: PP53.1 RB60.1 RS60.1
NetPP54_1: PP54.1 RB33.1 RS33.1
NetPP55_1: PP55.1 RB109.1 RS109.1
NetPP56_1: PP56.1 RB50.1 RS50.1
NetPP57_1: PP57.1 RB3.1 RS4.1
NetPP58_1: PP58.1 RB130.1 RS130.1
NetPP59_1: PP59.1 RB85.1 RS85.1
NetPP60_1: PP60.1 RB70.1 RS70.1
NetPP61_1: PP61.1 RB57.1 RS57.1
NetPP62_1: PP62.1 RB104.1 RS104.1
NetPP63_1: PP63.1 RB121.1 RS121.1
NetPP64_1: PP64.1 RB18.1 RS18.1
NetPP65_1: PP65.1 RB92.1 RS92.1
NetPP66_1: PP66.1 RB81.1 RS81.1
NetPP67_1: PP67.1 RB64.1 RS64.1
NetPP68_1: PP68.1 RB8.1 RS7.1
NetPP69_1: PP69.1 RB126.1 RS126.1
NetPP70_1: PP70.1 RB40.1 RS40.1
NetPP71_1: PP71.1 RB55.1 RS55.1
NetPP72_1: PP72.1 RB87.1 RS87.1
NetPP73_1: PP73.1 RB88.1 RS88.1
NetPP74_1: PP74.1 RB90.1 RS90.1
NetPP75_1: PP75.1 RB59.1 RS59.1
NetPP76_1: PP76.1 RB91.1 RS91.1
NetPP77_1: PP77.1 RB34.1 RS34.1
NetPP78_1: PP78.1 RB93.1 RS93.1
NetPP79_1: PP79.1 RB110.1 RS110.1
NetPP80_1: PP80.1 RB38.1 RS38.1
NetPP81_1: PP81.1 RB115.1 RS115.1
NetPP82_1: PP82.1 RB84.1 RS84.1
NetPP83_1: PP83.1 RB56.1 RS56.1
NetPP84_1: PP84.1 RB71.1 RS71.1
NetPP85_1: PP85.1 RB58.1 RS58.1
NetPP86_1: PP86.1 RB74.1 RS74.1
NetPP87_1: PP87.1 RB32.1 RS32.1
NetPP88_1: PP88.1 RB61.1 RS61.1
NetPP89_1: PP89.1 RB77.1 RS77.1
NetPP90_1: PP90.1 RB78.1 RS78.1
NetPP91_1: PP91.1 RB10.1 RS10.1
NetPP92_1: PP92.1 RB7.1 RS8.1
NetPP93_1: PP93.1 RB26.1 RS26.1
NetPP94_1: PP94.1 RB69.1 RS69.1
NetPP95_1: PP95.1 RB86.1 RS86.1
NetPP96_1: PP96.1 RB44.1 RS44.1
NetPP97_1: PP97.1 RB80.1 RS80.1
NetPP98_1: PP98.1 RB45.1 RS45.1
NetPP99_1: PP99.1 RB75.1 RS75.1
NetPP100_1: PP100.1 RB48.1 RS48.1
NetPP101_1: PP101.1 RB21.1 RS21.1
NetPP102_1: PP102.1 RB94.1 RS94.1
NetPP103_1: PP103.1 RB82.1 RS82.1
NetPP104_1: PP104.1 RB99.1 RS99.1
NetPP105_1: PP105.1 RB100.1 RS100.1
NetPP106_1: PP106.1 RB42.1 RS42.1
NetPP107_1: PP107.1 RB134.1 RS134.1
NetPP108_1: PP108.1 RB30.1 RS30.1
NetPP109_1: PP109.1 RB96.1 RS96.1
NetPP110_1: PP110.1 RB46.1 RS46.1
NetPP111_1: PP111.1 RB47.1 RS47.1
NetPP112_1: PP112.1 RB13.1 RS13.1
NetPP113_1: PP113.1 RB22.1 RS22.1
NetPP114_1: PP114.1 RB52.1 RS52.1
NetPP115_1: PP115.1 RB95.1 RS95.1
NetPP116_1: PP116.1 RB25.1 RS25.1
NetPP117_1: PP117.1 RB132.1 RS132.1
NetPP118_1: PP118.1 RB102.1 RS102.1
NetPP119_1: PP119.1 RB29.1 RS29.1
NetPP120_1: PP120.1 RB4.1 RS3.1
NetPP121_1: PP121.1 RB76.1 RS76.1
NetPP122_1: PP122.1 RB62.1 RS62.1
NetPP123_1: PP123.1 RB35.1 RS35.1
NetPP124_1: PP124.1 RB14.1 RS14.1
NetPP125_1: PP125.1 RB16.1 RS15.1
NetPP126_1: PP126.1 RB83.1 RS83.1
NetPP127_1: PP127.1 RB116.1 RS116.1
NetPP128_1: PP128.1 RB28.1 RS28.1
NetPP129_1: PP129.1 RB49.1 RS49.1
NetPP130_1: PP130.1 RB36.1 RS36.1
NetPP131_1: PP131.1 RB24.1 RS24.1
NetPP132_1: PP132.1 RB37.1 RS37.1
NetPP133_1: PP133.1 RB39.1 RS39.1
NetPP134_1: PP134.1 RB12.1 RS11.1
NetPP135_1: PP135.1 RB23.1 RS23.1

Not connected (* = marked no-connect by the designer): IC1 3(NC) 4(NC); J5 17 18 19 20

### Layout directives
net class PP: NetPP1_1, NetPP2_1, NetPP3_1, NetPP4_1, NetPP5_1, NetPP6_1, NetPP7_1, NetPP8_1, NetPP9_1, NetPP10_1, NetPP11_1, NetPP12_1, NetPP13_1, NetPP14_1, NetPP15_1, NetPP16_1, NetPP17_1, NetPP18_1, NetPP19_1, NetPP20_1, NetPP21_1, NetPP22_1, NetPP23_1, NetPP24_1, NetPP25_1, NetPP26_1, NetPP27_1, NetPP28_1, NetPP29_1, NetPP30_1, NetPP31_1, NetPP32_1, NetPP33_1, NetPP34_1, NetPP35_1, NetPP36_1, NetPP37_1, NetPP38_1, NetPP39_1, NetPP40_1, NetPP41_1, NetPP42_1, NetPP43_1, NetPP44_1, NetPP45_1, NetPP46_1, NetPP47_1, NetPP48_1, NetPP49_1, NetPP50_1, NetPP51_1, NetPP52_1, NetPP53_1, NetPP54_1, NetPP55_1, NetPP56_1, NetPP57_1, NetPP58_1, NetPP59_1, NetPP60_1, NetPP61_1, NetPP62_1, NetPP63_1, NetPP64_1, NetPP65_1, NetPP66_1, NetPP67_1, NetPP68_1, NetPP69_1, NetPP70_1, NetPP71_1, NetPP72_1, NetPP73_1, NetPP74_1, NetPP75_1, NetPP76_1, NetPP77_1, NetPP78_1, NetPP79_1, NetPP80_1, NetPP81_1, NetPP82_1, NetPP83_1, NetPP84_1, NetPP85_1, NetPP86_1, NetPP87_1, NetPP88_1, NetPP89_1, NetPP90_1, NetPP91_1, NetPP92_1, NetPP93_1, NetPP94_1, NetPP95_1, NetPP96_1, NetPP97_1, NetPP98_1, NetPP99_1, NetPP100_1, NetPP101_1, NetPP102_1, NetPP103_1, NetPP104_1, NetPP105_1, NetPP106_1, NetPP107_1, NetPP108_1, NetPP109_1, NetPP110_1, NetPP111_1, NetPP112_1, NetPP113_1, NetPP114_1, NetPP115_1, NetPP116_1, NetPP117_1, NetPP118_1, NetPP119_1, NetPP120_1, NetPP121_1, NetPP122_1, NetPP123_1, NetPP124_1, NetPP125_1, NetPP126_1, NetPP127_1, NetPP128_1, NetPP129_1, NetPP130_1, NetPP131_1, NetPP132_1, NetPP133_1, NetPP134_1, NetPP135_1

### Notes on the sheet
- (near C2) Open/short calibration channels
- Known capacitance calibration channels
- (near J8) P73
- (near J9) P49
- (near J8) P74
- (near J8) P75
- (near J8) P76
- (near J8) P77
- (near J8) P78
- (near J9) P50
- (near J9) P51
- (near J9) P52
- (near J9) P53
- (near J9) P54
- (near J6) P113
- (near J7) P97
- (near J8) P79
- (near J8) P80
- (near J8) P81
- (near J9) P55
- (near J9) P56
- (near J9) P57
- (near J10) P33
- (near J11) P17
- (near J12) P1
- (near J6) P114
- (near J6) P115
- (near J6) P116
- (near J6) P117
- (near J6) P118
- (near J7) P98
- (near J7) P99
- (near J7) P100
- (near J7) P101
- (near J7) P102
- (near J8) P82
- (near J8) P83
- (near J8) P84
- (near J8) P85
- (near J8) P86
- (near J9) P58
- (near J9) P59
- (near J9) P60
- (near J9) P61
- (near J9) P62
- (near J10) P34
- (near J10) P35
- (near J10) P36
- (near J10) P37
- (near J10) P38
- (near J11) P18
- (near J11) P19
- (near J11) P20
- (near J11) P21
- (near J11) P22
- (near J12) P2
- (near J12) P3
- (near J12) P4
- (near J12) P5
- (near J12) P6
- (near J5) P129
- (near J6) P119
- (near J6) P120
- (near J6) P121
- (near J7) P103
- (near J7) P104
- (near J7) P105
- (near J8) P87
- (near J8) P88
- (near J8) P89
- (near J9) P63
- (near J9) P64
- (near J9) P65
- (near J10) P39
- (near J10) P40
- (near J10) P41
- (near J11) P23
- (near J11) P24
- (near J11) P25
- (near J12) P7
- (near J12) P8
- (near J12) P9
- (near J5) P130
- (near J5) P131
- (near J5) P132
- (near J5) P133
- (near J5) P134
- (near J6) P122
- (near J6) P123
- (near J6) P124
- (near J6) P125
- (near J6) P126
- (near J7) P106
- (near J7) P107
- (near J7) P108
- (near J7) P109
- (near J7) P110
- (near J8) P90
- (near J8) P91
- (near J8) P92
- (near J8) P93
- (near J8) P94
- (near J9) P66
- (near J9) P67
- (near J9) P68
- (near J9) P69
- (near J9) P70
- (near J10) P42
- (near J10) P43
- (near J10) P44
- (near J10) P45
- (near J10) P46
- (near J11) P26
- (near J11) P27
- (near J11) P28
- (near J11) P29
- (near J11) P30
- (near J12) P10
- (near J12) P11
- (near J12) P12
- (near J12) P13
- (near J12) P14
- (near J5) P135
- (near J6) P127
- (near J6) P128
- (near J7) P111
- (near J7) P112
- (near J8) P95
- (near J8) P96
- (near J9) P71
- (near J9) P72
- (near J10) P47
- (near J10) P48
- (near J11) P31
- (near J11) P32
- (near J12) P15
- (near J12) P16
- Needle connection
- All resistors RB.. are not mounted
- https://gitlab.cern.ch/skulis/HGCSensorProbeCard
- Copyright CERN 2019.
  This documentation describes Open Hardware and is licensed under the CERN OHL v.1.2.
  You may redistribute and modify this documentation under the terms of the CERN OHL v.1.2. (http://ohwr.org/CERNOHL). This documentation is distributed WITHOUT ANY EXPRESS OR IMPLIED WARRANTY, INCLUDING OF MERCHANTABILITY, SATISFACTORY QUALITY AND FITNESS FOR A PARTICULAR PURPOSE.
  Please see the CERN OHL v.1.2 for applicable conditions.

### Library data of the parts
B1 B2 = PLATED_HOLE1.0_PAD1.5: Single Terminal Socket; Part Description: Plated Through Hole: Hole Dia.=1mm Pad Dia.=1.5mm,  IPC-7251 Level C; Mounted: No
C1 C10 = CC0603_100NF_50V_10%_X7R: Non-polarised capacitor; Part Description: SMD Multilayer Chip Ceramic Capacitor; Manufacturer: GENERIC; Manufacturer1 Part Number: 223858615649; Voltage: 50V; TC: X7R; Tolerance: ±10%
C2 = CC0603_1PF_50V_0.25PF_NP0: Non-polarised capacitor; Part Description: SMD Multilayer Chip Ceramic Capacitor; Manufacturer: GENERIC; Manufacturer1 Part Number: 223886715108; Voltage: 50V; TC: C0G/NP0; Tolerance: ±0.25pF
C3 = CC0603_2.2PF_50V_0.25PF_NP0: Non-polarised capacitor; Part Description: SMD Multilayer Chip Ceramic Capacitor; Manufacturer: GENERIC; Manufacturer1 Part Number: 223886715228; Voltage: 50V; TC: C0G/NP0; Tolerance: ±0.25pF
C4 = CC0603_4.7PF_50V_0.25PF_NP0: Non-polarised capacitor; Part Description: SMD Multilayer Chip Ceramic Capacitor; Manufacturer: GENERIC; Manufacturer1 Part Number: 223886715478; Voltage: 50V; TC: C0G/NP0; Tolerance: ±0.25pF
C5 = CC0603_10PF_50V_5%_NP0: Non-polarised capacitor; Part Description: SMD Multilayer Chip Ceramic Capacitor; Manufacturer: GENERIC; Manufacturer1 Part Number: 223886715109; Voltage: 50V; TC: C0G/NP0; Tolerance: ±5%
C6 = CC0603_22PF_50V_5%_NP0: Non-polarised capacitor; Part Description: SMD Multilayer Chip Ceramic Capacitor; Manufacturer: GENERIC; Manufacturer1 Part Number: 223886715229; Voltage: 50V; TC: C0G/NP0; Tolerance: ±5%
C7 = CC0603_47PF_50V_5%_NP0: Non-polarised capacitor; Part Description: SMD Multilayer Chip Ceramic Capacitor; Manufacturer: GENERIC; Manufacturer1 Part Number: 223886715479; Voltage: 50V; TC: C0G/NP0; Tolerance: ±5%
C8 = CC0603_100PF_50V_5%_NP0: Non-polarised capacitor; Part Description: SMD Multilayer Chip Ceramic Capacitor; Manufacturer: GENERIC; Manufacturer1 Part Number: 223886715101; Voltage: 50V; TC: C0G/NP0; Tolerance: ±5%
C9 = CC0603_220PF_50V_5%_NP0: Non-polarised capacitor; Part Description: SMD Multilayer Chip Ceramic Capacitor; Manufacturer: GENERIC; Manufacturer1 Part Number: 223886715221; Voltage: 50V; TC: C0G/NP0; Tolerance: ±5%
FTG1-FTG3 = FIDUCIAL_TARGET_C100-200: Fiducial Target; Part Description: Round Fiducial Target, Top Layer, 1.0mm, Top Solder 2.0mm, Keepout =2.0mm; Mounted: No
Graphical = SHT75: Humidity and Temperature Sensor IC; Part Description: 2-Wire Serial Interface Digital Humidity 0 – 100% RH and Temperature -40°C to +125°C Sensor; Manufacturer: SENSIRION; PressFit: No; Bonding: No
IC1 = SHT25: Humidity and Temperature Sensor IC; Part Description: I2C Digital Humidity 0 – 100% RH and Temperature -40°C to +125°C Sensor; Manufacturer: SENSIRION; PressFit: No; Bonding: No; Sense Comment: Non-washable
J1 J4 = SAMTEC_MTLW-106-07-L-D-250: Connector 12 Male; Part Description: 12 Contacts, Pitch 2.54mm, Dual Row Through Mount Straight Header (Post Lead = 6.35mm, Tail Lead 3.05mm, Insulator 1.52mm); Manufacturer: SAMTEC; PressFit: No
J2 = LEMO_EPK.00.250.NTN: Part Description: Size 00, 50 Ohms Coaxial Elbow (90°) socket With Clearance Under The Body; PressFit: No; SCEM: 09.46.11.180.6
J3 = SAMTEC_SSW-104-02-L-S-RA: Connector 4 Female; Part Description: 4 Contacts, Pitch 2.54mm, Single Row Through Mount Right Angle Socket (Lead Length 2.54mm); Manufacturer: SAMTEC; PressFit: No
J5 J8 J9 = SAMTEC_MTLW-116-07-L-D-250: Connector 32 Male; Part Description: 32 Contacts, Pitch 2.54mm, Dual Row Through Mount Straight Header (Post Lead = 6.35mm, Tail Lead 3.05mm, Insulator 1.52mm); Manufacturer: SAMTEC; PressFit: No
J6 J7 J10-J12 = SAMTEC_MTLW-111-07-L-D-250: Connector 20 Male; Part Description: 22 Contacts, Pitch 2.54mm, Dual Row Through Mount Straight Header (Post Lead = 6.35mm, Tail Lead 3.05mm, Insulator 1.52mm); Manufacturer: SAMTEC; PressFit: No
NT1 NT2 = Net Tie: Part Description: Net Tie (2 Nets); Mounted: No
PP1-PP135 = MILL-MAX_0985-1-15-20-71-14-11-0: Test Point; Part Description: Probe, Spring-Loaded Pin, 2A Continuous, 3A Peak, -55..125°C (Soldered Pin 3.81mm); PressFit: No
R1-R3 = R0603_10K_1%_0.1W_100PPM: Resistor - 1%; Part Description: General Purpose Thick Film Chip Resistor; Manufacturer: GENERIC; Manufacturer1 Part Number: NRC06F1002TRF; Power: 0.1W; TC: ±100ppm/°C; Mounted: No; Pressfit: No
R4 = R0603_10K_1%_0.1W_100PPM: Resistor - 1%; Part Description: General Purpose Thick Film Chip Resistor; Manufacturer: GENERIC; Manufacturer1 Part Number: NRC06F1002TRF; Power: 0.1W; TC: ±100ppm/°C; Pressfit: No
RB1-RB135 = R0603_10M_1%_0.125W_100PPM_VISHAY_CHP: Resistor - 1%; Part Description: High Stability Metal Glaze Thick Film Chip Resistor; Manufacturer: VISHAY SFERNICE; Manufacturer Part Number: CHP0603K1005FNT; Power: 0.125W; TC: ±100ppm/°C; Mounted: No; Pressfit: No
RS1-RS135 = R0603_0R_JUMPER: Resistor; Part Description: 1A (0.05R Max DC Resistance) Zero Ohm Jumper; Manufacturer: GENERIC; Manufacturer1 Part Number: NRC06Z0; Pressfit: No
